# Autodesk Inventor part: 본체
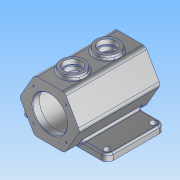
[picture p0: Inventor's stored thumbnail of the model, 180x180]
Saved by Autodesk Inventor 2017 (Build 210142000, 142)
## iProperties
Part Number: 본체
Material: 알루미늄 6061
Document SubType Name: Modeling
Designer: user
Density: 2.7 g/cm^3
Appearance: 알루미늄 - 평지
Mass: 1495.24 g
Surface Area: 1102.33 cm^2
Volume: 553.791 cm^3
Author: user
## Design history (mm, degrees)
sketch "스케치1"
  geometry: L1 (-50, 75)-(50, 75); L2 (50, 75)-(50, -75); L3 (50, -75)-(-50, -75); L4 (-50, -75)-(-50, 75); L5 (-50, 75)-(50, -75); L6 (50, 75)-(-50, -75); 1 further point
  constraints: 12 end point, 2 midpoint, 2 parallel, 1 horizontal, 1 perpendicular
  dimensions: "d0" = 100 distance of L2.end L3.end; "d1" = 150 distance of L3.end L1.start
extrude "돌출1" new body sketch "스케치1" distance "d2" = 12; taper "d3" = 0 deg
sketch "스케치3" dims "d5" = 105
  geometry: L1 (75, 0)-(-75, 0) reference; L2 (52.5, 50)-(26.25, 4.534); L3 (26.25, 4.534)-(-26.25, 4.534); L4 (-26.25, 4.534)-(-52.5, 50); L5 (-52.5, 50)-(-26.25, 95.466); L6 (-26.25, 95.466)-(26.25, 95.466); L7 (26.25, 95.466)-(52.5, 50); 3 further points
  constraints: 12 end point, 1 coincident, 1 horizontal alignment, 15 other
  dimensions: "d4" = 50 distance from line of L1 point (0, 50)
extrude "돌출2" join sketch "스케치3" distance "d6" = 75; taper "d8" = 0 deg; dims "d7" = 65, "d9" = 0
sketch "스케치4"
  geometry: L1 (-95.466, -26.25)-(-4.534, 26.25); C1 r 30 at (-50, 0); 1 further point
  constraints: 2 end point, 1 centre point, 1 midpoint
  dimensions: "d10" = 60 diameter of C1
extrude "돌출3" cut sketch "스케치4" distance "d11" = 186.25; taper "d12" = 0 deg
sketch "스케치5"
  geometry: L1 (-50, 0)-(-78.284, 28.284); L2 (-50, 0)-(-50, 40); C1 r 30 at (-50, 0) reference; A1 r 40 centre (-50, 0) between (-78.284, 28.284) and (-50, 40); 2 further points
  constraints: 4 end point, 2 coincident, 2 point on circle, 1 centre point, 1 vertical alignment
  dimensions: "d13" = 80 diameter of A1; "d14" = 45 deg angle of L2 L1
hole "구멍1" sketch "스케치5" at (-78.284, 28.284) diameter "d15" = 3.242; stored, may be unused: countersink angle "d19" = 90 deg, drill point angle "d21" = 118 deg; dims "d16" = 8, "d17" = 4, "d18" = 2, "d20" = 10
sketch "스케치6" dims "d25" = 80
  geometry: L1 (50, 0)-(90, 0); C1 r 30 at (50, 0) reference; 2 further points
  constraints: 2 coincident, 2 end point, 1 horizontal, 1 horizontal alignment, 2 other
hole "구멍2" sketch "스케치6" at (90, 0) diameter "d26" = 3.242; stored, may be unused: countersink angle "d30" = 90 deg, drill point angle "d32" = 118 deg; dims "d27" = 8, "d28" = 4, "d29" = 2, "d31" = 10
fillet "모깎기1" dims "d36" = 10
hole "구멍3" diameter "d39" = 11; stored, may be unused: countersink angle "d43" = 90 deg, drill point angle "d45" = 0 deg; dims "d37" = 10, "d38" = 10, "d40" = 10, "d41" = 4, "d42" = 2, "d44" = 30
hole "구멍4" diameter "d48" = 11; stored, may be unused: countersink angle "d52" = 90 deg, drill point angle "d54" = 0 deg; dims "d46" = 10, "d47" = 10, "d49" = 10, "d50" = 4, "d51" = 2, "d53" = 30
hole "구멍5" diameter "d57" = 11; stored, may be unused: countersink angle "d61" = 90 deg, drill point angle "d63" = 0 deg; dims "d55" = 10, "d56" = 10, "d58" = 10, "d59" = 4, "d60" = 2, "d62" = 30
hole "구멍6" diameter "d66" = 11; stored, may be unused: countersink angle "d70" = 90 deg, drill point angle "d72" = 0 deg; dims "d64" = 10, "d65" = 10, "d67" = 10, "d68" = 4, "d69" = 2, "d71" = 30
node "작업 평면1"
sketch "스케치8"
  geometry: L1 (75, 26.25)-(75, -26.25) reference; C1 r 20 at (35, 0); C2 r 20 at (-25, 0); 1 further point
  constraints: 2 centre point, 2 horizontal alignment
  dimensions: "d76" = 40 diameter of C1; "d77" = 40 diameter of C2; "d78" = 40 distance from line of C1.centre L1; "d79" = 60 distance of C2.centre C1.centre
extrude "돌출4" join sketch "스케치8" stored distance "d80" = 186.25; taper "d81" = 0 deg
sketch "스케치9"
  geometry: C1 r 20 at (0, 0) reference; C2 r 15 at (0, 0); 1 further point
  constraints: 1 centre point, 1 coincident
  dimensions: "d82" = 30 diameter of C2
extrude "돌출5" cut sketch "스케치9" distance "d83" = 8; taper "d84" = 0 deg
sketch "스케치10"
  geometry: C1 r 15 at (0, 0) reference; C2 r 12.5 at (0, 0); 1 further point
  constraints: 1 centre point, 1 coincident
  dimensions: "d85" = 25 diameter of C2
extrude "돌출6" cut sketch "스케치10" distance "d86" = 40; taper "d87" = 0 deg
sketch "스케치11"
  geometry: C1 r 20 at (0, 0) reference; C2 r 15 at (0, 0); 1 further point
  constraints: 1 centre point, 1 coincident
  dimensions: "d88" = 30 diameter of C2
extrude "돌출7" cut sketch "스케치11" distance "d89" = 8; taper "d90" = 0 deg
sketch "스케치12"
  geometry: C1 r 15 at (0, 0) reference; C2 r 12.5 at (0, 0); 1 further point
  constraints: 1 centre point, 1 coincident
  dimensions: "d91" = 25 diameter of C2
extrude "돌출8" cut sketch "스케치12" distance "d92" = 40.75; taper "d93" = 0 deg
chamfer "모따기1" distance "d94" = 1; stored, may be unused: second distance "d95" = 2, angle "d96" = 45 deg
sketch "스케치13"
  geometry: L1 (-75, 20)-(-75, 80) reference; L2 (65, 80)-(65, 20) reference; L3 (-75, 50)-(65, 50); L4 (-75, 80)-(65, 80) reference; L5 (-63, 80)-(-63, 87.5); L6 (-63, 87.5)-(53, 87.5); L7 (53, 87.5)-(53, 80); L8 (-75, 95.466)-(-75, 50) reference; L9 (65, 50)-(65, 95.466) reference; 1 further point
  constraints: 8 end point, 2 midpoint, 2 point on line, 1 parallel, 1 perpendicular, 1 vertical
  dimensions: "d97" = 75 diameter of L6 L3; "d98" = 12 distance between parallel lines of L5 L8; "d99" = 12 distance between parallel lines of L9 L7
revolve "회전1" sketch "스케치13" stored, may be unused: angle "d100" = 90 deg
fillet "모깎기2" dims "d101" = 8
fillet "모깎기3" dims "d102" = 5
chamfer "모따기2" distance "d103" = 1; stored, may be unused: second distance "d104" = 2, angle "d105" = 45 deg
fillet "모깎기4" dims "d106" = 3
fillet "모깎기5" dims "d107" = 3
fillet "모깎기6" dims "d108" = 3
sketch "스케치14"
  geometry: L1 (40, -72)-(-40, -72) reference; L2 (-20.739, -57.998)-(20.739, -57.998); L3 (20.739, -57.998)-(20.739, -64.002); L4 (20.739, -64.002)-(-20.739, -64.002); L5 (-20.739, -64.002)-(-20.739, -57.998); L6 (-20.739, -57.998)-(20.739, -64.002); L7 (-40, -75)-(40, -75) reference; L8 (50, -65)-(50, -35.757) reference; 3 further points
  constraints: 2 end point, 2 midpoint, 1 vertical alignment, 2 other
  dimensions: "d109" = 14 distance from line of L7 point (0, -61); "d110" = 50 distance from line of L8 point (0, -61) (derived)
extrude "돌출9" cut sketch "스케치14" distance "d111" = 0.5; taper "d112" = 0 deg
node "솔리드1"
pattern_circular "원형 패턴1" dims angle "d23" = 360 deg
pattern_circular "원형 패턴2" dims angle "d34" = 360 deg
other parameters: "d75" = 102.5
